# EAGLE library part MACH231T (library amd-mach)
AMD MACH SERIES
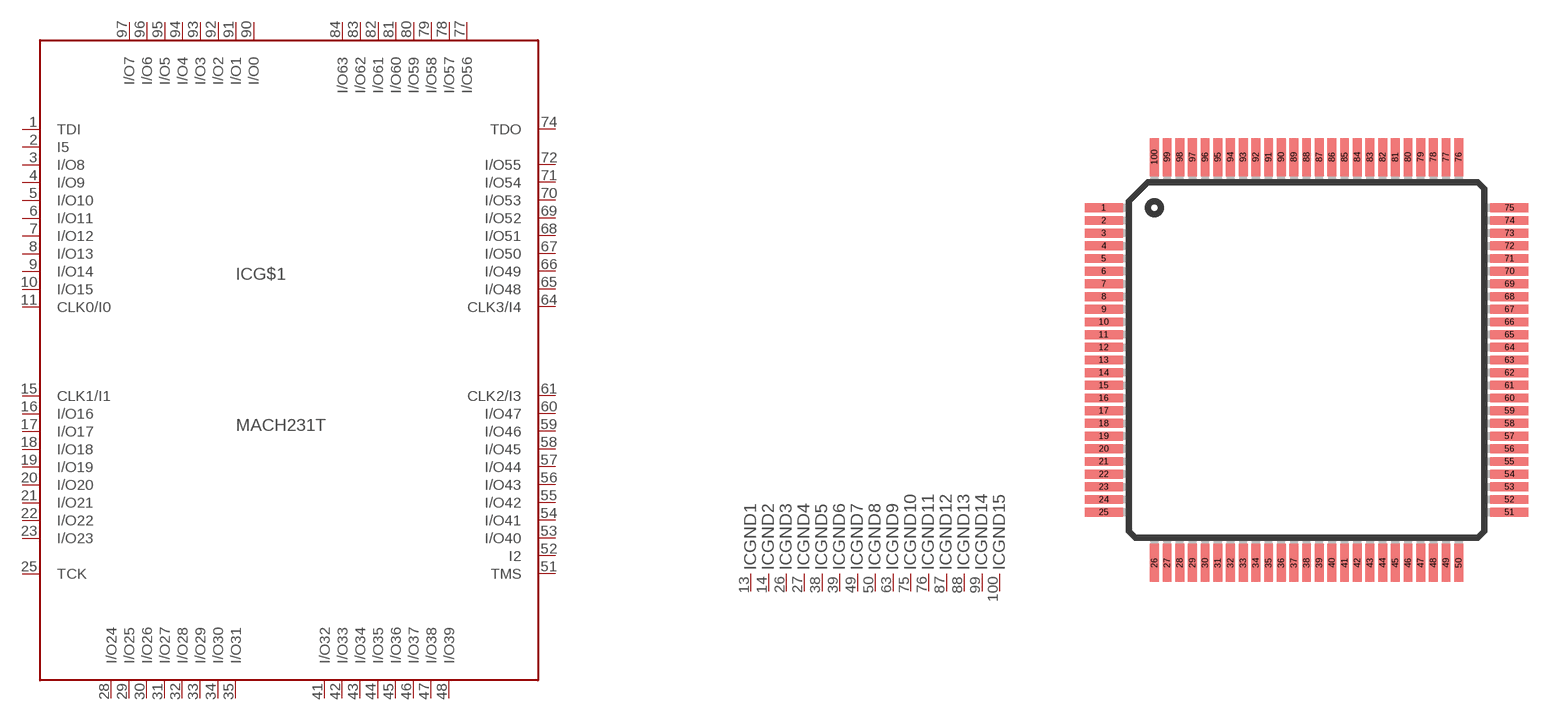
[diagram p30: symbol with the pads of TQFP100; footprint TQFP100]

Designator prefix IC; gates G$1=MACH231P GND1=GND GND2=GND GND3=GND GND4=GND GND5=GND GND6=GND GND7=GND GND8=GND GND9=GND GND10=GND GND11=GND GND12=GND GND13=GND GND14=GND GND15=GND VCC1=VCC VCC2=VCC VCC3=VCC VCC4=VCC VCC5=VCC VCC6=VCC NC1=NC NC2=NC NC3=NC NC4=NC NC5=NC

## MACH231T (OC_FARNELL: unknown; OC_NEWARK: unknown)  [TQFP100]
1  G$1:TDI  in
2  G$1:I5  in
3  G$1:I/O8
4  G$1:I/O9
5  G$1:I/O10
6  G$1:I/O11
7  G$1:I/O12
8  G$1:I/O13
9  G$1:I/O14
10  G$1:I/O15
11  G$1:CLK0/I0  in
12  VCC1:VCC  pwr
13  GND1:GND  pwr
14  GND2:GND  pwr
15  G$1:CLK1/I1  in
16  G$1:I/O16
17  G$1:I/O17
18  G$1:I/O18
19  G$1:I/O19
20  G$1:I/O20
21  G$1:I/O21
22  G$1:I/O22
23  G$1:I/O23
24  NC1:NC  nc
25  G$1:TCK  in
26  GND3:GND  pwr
27  GND4:GND  pwr
28  G$1:I/O24
29  G$1:I/O25
30  G$1:I/O26
31  G$1:I/O27
32  G$1:I/O28
33  G$1:I/O29
34  G$1:I/O30
35  G$1:I/O31
36  NC2:NC  nc
37  VCC2:VCC  pwr
38  GND5:GND  pwr
39  GND6:GND  pwr
40  VCC3:VCC  pwr
41  G$1:I/O32
42  G$1:I/O33
43  G$1:I/O34
44  G$1:I/O35
45  G$1:I/O36
46  G$1:I/O37
47  G$1:I/O38
48  G$1:I/O39
49  GND7:GND  pwr
50  GND8:GND  pwr
51  G$1:TMS  in
52  G$1:I2  in
53  G$1:I/O40
54  G$1:I/O41
55  G$1:I/O42
56  G$1:I/O43
57  G$1:I/O44
58  G$1:I/O45
59  G$1:I/O46
60  G$1:I/O47
61  G$1:CLK2/I3  in
62  VCC4:VCC  pwr
63  GND9:GND  pwr
64  G$1:CLK3/I4  in
65  G$1:I/O48
66  G$1:I/O49
67  G$1:I/O50
68  G$1:I/O51
69  G$1:I/O52
70  G$1:I/O53
71  G$1:I/O54
72  G$1:I/O55
73  NC3:NC  nc
74  G$1:TDO  in
75  GND10:GND  pwr
76  GND11:GND  pwr
77  G$1:I/O56
78  G$1:I/O57
79  G$1:I/O58
80  G$1:I/O59
81  G$1:I/O60
82  G$1:I/O61
83  G$1:I/O62
84  G$1:I/O63
85  NC4:NC  nc
86  VCC5:VCC  pwr
87  GND12:GND  pwr
88  GND13:GND  pwr
89  VCC6:VCC  pwr
90  G$1:I/O0
91  G$1:I/O1
92  G$1:I/O2
93  G$1:I/O3
94  G$1:I/O4
95  G$1:I/O5
96  G$1:I/O6
97  G$1:I/O7
98  NC5:NC  nc
99  GND14:GND  pwr
100  GND15:GND  pwr

## Footprint TQFP100 (pad centres in mm)
THIN QUAD FLAT PACK
smd 1.5 x 0.35: 1 -8,6; 2 -8,5.5; 3 -8,5; 4 -8,4.5; 5 -8,4; 6 -8,3.5; 7 -8,3; 8 -8,2.5; 9 -8,2; 10 -8,1.5; 11 -8,1; 12 -8,0.5; 13 -8,0; 14 -8,-0.5; 15 -8,-1; 16 -8,-1.5; 17 -8,-2; 18 -8,-2.5; 19 -8,-3; 20 -8,-3.5; 21 -8,-4; 22 -8,-4.5; 23 -8,-5; 24 -8,-5.5; 25 -8,-6; 51 8,-6; 52 8,-5.5; 53 8,-5; 54 8,-4.5; 55 8,-4; 56 8,-3.5; 57 8,-3; 58 8,-2.5; 59 8,-2; 60 8,-1.5; 61 8,-1; 62 8,-0.5; 63 8,0; 64 8,0.5; 65 8,1; 66 8,1.5; 67 8,2; 68 8,2.5; 69 8,3; 70 8,3.5; 71 8,4; 72 8,4.5; 73 8,5; 74 8,5.5; 75 8,6
smd 0.35 x 1.5: 26 -6,-8; 27 -5.5,-8; 28 -5,-8; 29 -4.5,-8; 30 -4,-8; 31 -3.5,-8; 32 -3,-8; 33 -2.5,-8; 34 -2,-8; 35 -1.5,-8; 36 -1,-8; 37 -0.5,-8; 38 0,-8; 39 0.5,-8; 40 1,-8; 41 1.5,-8; 42 2,-8; 43 2.5,-8; 44 3,-8; 45 3.5,-8; 46 4,-8; 47 4.5,-8; 48 5,-8; 49 5.5,-8; 50 6,-8; 76 6,8; 77 5.5,8; 78 5,8; 79 4.5,8; 80 4,8; 81 3.5,8; 82 3,8; 83 2.5,8; 84 2,8; 85 1.5,8; 86 1,8; 87 0.5,8; 88 0,8; 89 -0.5,8; 90 -1,8; 91 -1.5,8; 92 -2,8; 93 -2.5,8; 94 -3,8; 95 -3.5,8; 96 -4,8; 97 -4.5,8; 98 -5,8; 99 -5.5,8; 100 -6,8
